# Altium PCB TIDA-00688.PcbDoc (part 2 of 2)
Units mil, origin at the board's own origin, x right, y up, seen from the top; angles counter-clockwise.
Board outline 1000 x 2450.32 mil, 4 copper layers (Top Layer, Signal Layer 1, Signal Layer 2, Bottom Layer), stack 61.6 mil thick; 78 components, 39 nets, 179 pads, 94 vias.
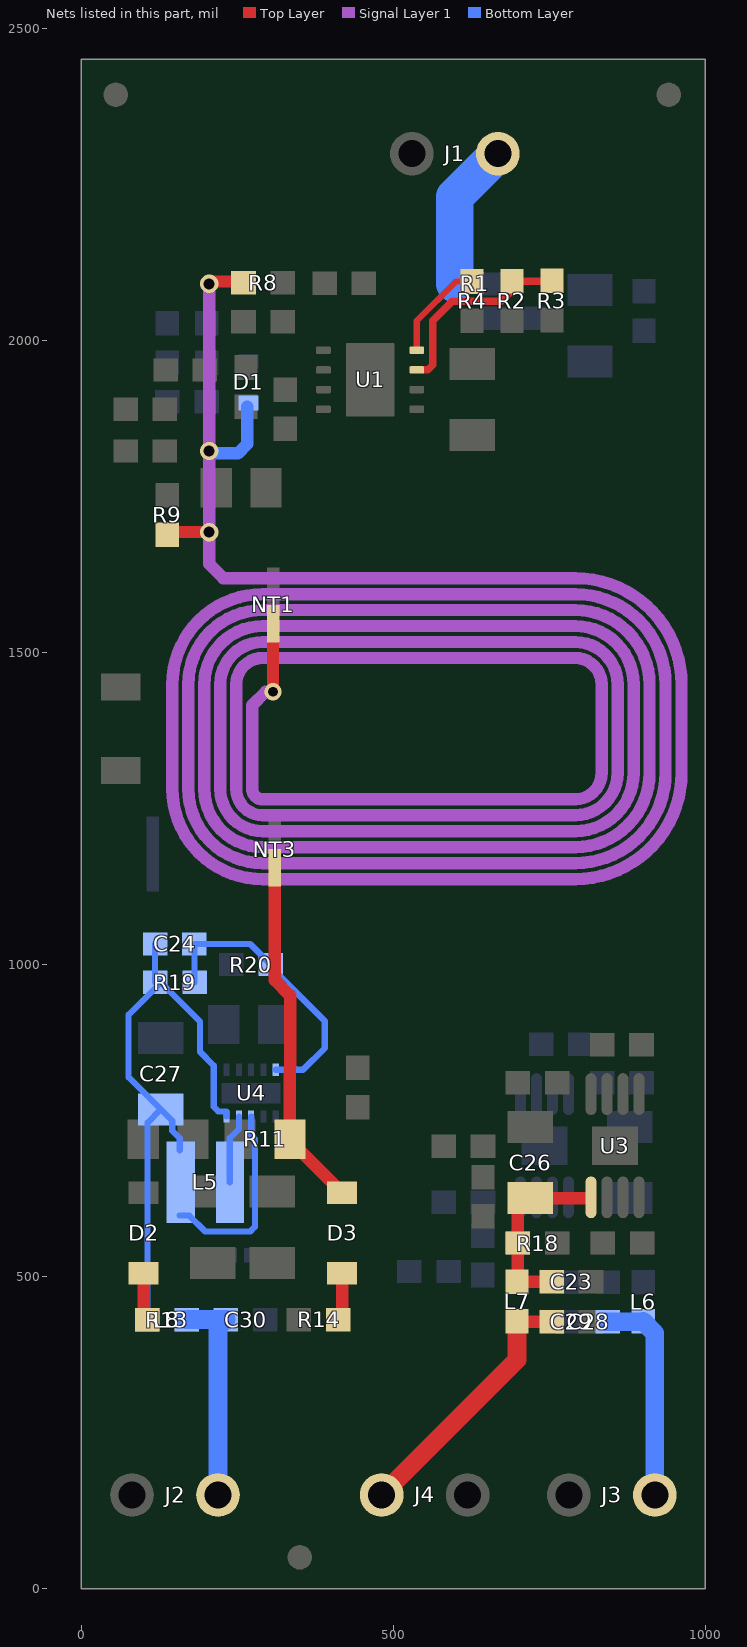
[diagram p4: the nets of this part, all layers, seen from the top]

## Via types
v1: diameter 26, hole 12, Top Layer to Bottom Layer, tented both sides, 55 vias
v2: diameter 20, hole 7.87, Top Layer to Bottom Layer, 10 vias
v3: diameter 29.53, hole 17.72, Top Layer to Bottom Layer, 8 vias
v4: diameter 20, hole 8, Top Layer to Bottom Layer, tented both sides, 7 vias
v5: diameter 19.68, hole 7.87, Top Layer to Bottom Layer, 6 vias
v6: diameter 23.62, hole 11.81, Top Layer to Bottom Layer, 3 vias
v7: diameter 26, hole 8, Top Layer to Bottom Layer, tented both sides, 2 vias
v8: diameter 24, hole 10, Top Layer to Bottom Layer, 1 vias
v9: diameter 20, hole 8, Top Layer to Bottom Layer, 1 vias
v10: diameter 27.56, hole 15.75, Top Layer to Bottom Layer, 1 vias

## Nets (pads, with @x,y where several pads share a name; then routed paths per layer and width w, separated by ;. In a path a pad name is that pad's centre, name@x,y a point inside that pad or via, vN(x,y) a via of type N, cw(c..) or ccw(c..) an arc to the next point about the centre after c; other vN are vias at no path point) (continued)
NetC23_2: C23.2 C26.1 L7.1 R18.2 U3.1 | length 296.5
  Top Layer w20: C23.2@753.5,491.7 700.5,491.7 699.5,492.7 R18.2@699.5,553.7 699.5,614.5 710.61,625.61 C26.1@719,625.61 U3.1@815.21,625.61
NetC24_1: C24.1 C27.1 L5.2 L8.1 R19.2 U4.8 U4.10 | length 1321.1
  Bottom Layer w10: L8.1@104.88,431 106,432.12 106,746.79 C27.1@127.13,767.91 ; C24.1@118.11,1032.89 118.11,971.67 R19.2@118.32,971.46 R19.2@127.59,971.46 ; L5.2@157.61,597.64 173.13,597.64 198.6,572.17 270.42,572.17 277.96,579.71 277.96,720.04 272,726 U4.8@272,756.6 ; L5.2@157.61,702.36 157.61,721.54 145.38,733.76 145.38,749.66 C27.1@127.13,767.91 ; U4.10@232.63,756.6 232.63,764.59 219.42,764.59 211.88,772.13 211.88,838.03 190.13,859.79 190.13,908.3 127.59,970.84 R19.2@127.59,971.46 ; C27.1@127.13,767.91 75.5,819.54 75.5,919.37 R19.2@127.59,971.46
NetC24_2: C24.2 R19.1 R20.2 U4.5 | length 459.7
  Bottom Layer w10: R19.1@181.32,971.46 181.31,1032.68 C24.2@181.1,1032.89 270.26,1032.89 R20.2@303.15,1000 303.15,996.06 389.76,909.45 389.76,866.14 355.02,831.4 U4.5@311.37,831.4
NetC28_1: C28.1 J3.2 L6.2 | length 398.7
  Bottom Layer w20: C28.1@843.5,427.7 L6.2@899.5,427.7
  Bottom Layer w30: C28.1@843.5,427.7 899.5,427.7 L6.2@900,428.2 918.9,409.31 J3.2@918.9,150
NetC29_1: C29.1 J4.1 L7.2 | length 423.1
  Top Layer w20: L7.2@698.7,427.7 C29.1@753.5,427.7
  Top Layer w30: J4.1@481.1,150 698,366.9 L7.2@698,428.5
NetC30_1: C30.1 J2.2 L8.2 | length 349.2
  Bottom Layer w30: L8.2@168.5,431 C30.1@231.5,431 218.9,418.39 J2.2@218.9,150
NetD1_2: D1.2 NT1.2 R8.2 R9.2 | length 12283.4
  Top Layer w19.68: R9.2@137.8,1688.98 141.73,1692.91 v3(204.72,1692.91) ; v3(204.72,2090.55) 208.68,2094.49 R8.2@259.84,2094.49 ; v10(307.09,1437.01) v10(307.09,1437.01) NT1.2@307.13,1546.33
  Signal Layer 1 w19.68: v3(204.72,2090.55) v3(204.72,1692.91) 204.72,1641.73 227.36,1619.09 791.34,1619.09 cw(c791.34,1448.82) 961.61,1448.82 961.61,1307.09 cw(c791.34,1307.09) 791.34,1136.81 290.35,1136.81 cw(c290.35,1281.5) 145.67,1281.5 145.67,1448.82 cw(c290.35,1448.82) 290.35,1593.5 791.34,1593.5 cw(c791.34,1448.82) 936.02,1448.82 936.02,1307.09 cw(c791.34,1307.09) 791.34,1162.4 290.35,1162.4 cw(c290.35,1281.5) 171.26,1281.5 171.26,1448.82 cw(c290.35,1448.82) 290.35,1567.91 791.56,1567.91 cw(c791.56,1449.04) 910.43,1449.04 910.43,1307.09 cw(c791.34,1307.09) 791.34,1187.99 290.35,1187.99 cw(c290.35,1281.5) 196.85,1281.5 196.85,1448.82 cw(c290.35,1448.82) 290.35,1542.32 791.34,1542.32 cw(c791.34,1448.82) 884.84,1448.82 884.84,1307.09 cw(c791.34,1307.09) 791.34,1213.58 290.35,1213.58 cw(c290.35,1281.5) 222.44,1281.5 222.44,1448.82 cw(c290.35,1448.82) 290.35,1516.73 791.34,1516.73 cw(c791.34,1448.82) 859.25,1448.82 859.25,1307.09 cw(c791.34,1307.09) 791.34,1239.17 290.35,1239.17 cw(c290.35,1281.5) 248.03,1281.5 248.03,1448.82 cw(c290.35,1448.82) 290.35,1491.14 791.34,1491.14 cw(c791.34,1448.82) 833.66,1448.82 833.66,1307.09 cw(c791.34,1307.09) 791.34,1264.76 290.25,1264.76 cw(c290.25,1281.5) 273.52,1281.5 273.52,1415.25 295.28,1437.01 v10(307.09,1437.01)
  Bottom Layer w19.68: v3(204.72,1822.83) 204.72,1818.9 204.92,1819.09 250.69,1819.09 265.75,1834.14 D1.2@265.75,1893.7
NetD2_1: D2.1 R13.2 | length 76.9
  Top Layer w20: D2.1@99.69,505.53 99.69,436.82 R13.2@105.5,431
NetD3_1: D3.1 NT3.2 R11.2 | length 563.3
  Top Layer w20: NT3.2@309.94,1155.04 309.94,974.97 334.49,950.42 R11.2@334,720 ; R11.2@334.11,717.96 D3.1@417.6,634.47
NetD3_2: D3.2 R14.2 | length 77.1
  Top Layer w20: R14.2@411.5,431 417.6,437.1 D3.2@417.6,505.53
NetJ1_1: J1.1 R1.2 | length 237.2
  Bottom Layer w60: R1.2@598.43,2090.55 598.43,2230.32 J1.1@667.32,2299.21
NetL5_1: L5.1 U4.9 | length 111.6
  Bottom Layer w10: L5.1@237.87,651 237.87,721.87 252.32,736.32 U4.9@252.31,756.6
NetR2_1: R2.1 R3.2 U1.3 | length 326.1
  Top Layer w11.81: U1.3@537.4,1952.75 555.11,1952.75 562.99,1960.63 562.99,2031.5 594.49,2062.99 673.23,2062.99 689.9,2079.67 R2.1@689.9,2094.85 753.31,2094.85 R3.2@753.94,2095.47
NetR4_2: R4.2 U1.4 | length 161.9
  Top Layer w10: U1.4@537.4,1984.25 537.4,2031.5 600.39,2094.49 R4.2@625.98,2094.49
pads on no net: FID1.1 FID2.1 FID3.1 U2.3 U2.7 U3.3 U3.7 U4.4

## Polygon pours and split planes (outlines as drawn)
GNDS on Bottom Layer "Top Layer-No Net 1" (solid, remove dead copper, shelved, pour order 17): 7.02,1075.61 7.02,1326.7 12.99,1332.67 93.19,1332.67 94.61,1331.24 94.61,1113.83 94.61,1112.4 82.85,1100.64 83.21,1100.28 83.21,1075.61
GND on Bottom Layer "Top Layer-No Net" (solid, remove dead copper, pour order 20): 15.26,1420.89 97.94,1420.89 101.88,1424.82 101.88,1538.22 220.48,1656.82 322.06,1656.82 326.28,1661.04 326.28,1767.34 381.4,1822.46 976,1822.46 987.7,1834.16 987.7,2111.99 973.67,2126.02 29.59,2126.02 11.32,2107.76 11.32,1432.7 23.14,1420.89
GNDS on Bottom Layer "Top Layer-No Net 3" (solid, remove dead copper, pour order 18): 0,1082.68 0,401.14 552,401.14 552,1082.68
GNDA on Bottom Layer "Top Layer-No Net 2" (solid, remove dead copper, pour order 14): 447,394.62 1000,394.62 1000,410 447,410
GNDA on Bottom Layer "Bottom Layer-No Net 1" (solid, remove dead copper, pour order 12): 1000,944.88 557,944.88 557,400 1000,400
GND on Top Layer "Top Layer-No Net" (solid, remove dead copper, pour order 19): 93.56,1420.94 102.36,1429.74 102.36,1539.37 220.06,1657.07 322.31,1657.07 326.28,1661.04 326.28,1767.47 381.65,1822.83 866.14,1822.83 976.38,1822.83 988.19,1834.65 988.19,2111.51 973.36,2126.33 29.9,2126.33 11.81,2108.24 11.81,1432.21 23.08,1420.94
GNDA on Top Layer "Top Layer-No Net 2" (solid, remove dead copper, pour order 13): 447,400 1000,400 1000,420 447,420
GNDA on Top Layer "Top Layer-GNDA" (solid, pour order 11): 1000,944.88 560,944.88 560,400 1000,400
GNDS on Top Layer "Top Layer-No Net 3" (solid, remove dead copper, pour order 15): 0,1082.68 0,400 552,400 552,1082.68
GNDS on Top Layer "Top Layer-No Net 1" (solid, remove dead copper, pour order 16): 7.02,1075.61 7.02,1326.7 12.99,1332.67 93.19,1332.67 94.61,1331.24 94.61,1113.83 94.61,1112.4 82.85,1100.64 83.21,1100.28 83.21,1075.61

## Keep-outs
Keep-Out Layer:
  lines w3.94: 0,0 1000,0 1000,2450.32 0,2450.32 0,0 ; 405.51,944.88 799.21,944.88 799.21,1102.36 405.51,1102.36 405.51,944.88 ; 405.51,1299.21 799.21,1299.21 799.21,1456.69 405.51,1456.69 405.51,1299.21 ; 405.51,1653.54 799.21,1653.54 799.21,1811.02 405.51,1811.02 405.51,1653.54
  lines w5: 359.7,3393.23 cw(c362.2,3393.23) 362.2,3395.73 ccw(c362.2,3393.23) 359.7,3393.23 ; 1000,2958.72 cw(c1000,2956.22) 1002.5,2956.22 ccw(c1000,2956.22) 1000,2958.72
  text ".Layer_Name" at 577,-858.49 h60

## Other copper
Top Layer:
  pour cut-out: 450,0 430,0 430,205.34 546,321.34 546,937.86 566.02,937.86 566.01,321.01 450,205 450,118
  pour cut-out: 409.45,944.88 362.2,944.88 326.77,980.32 326.77,1102.36 409.45,1102.36
  text ".CopyrightYear" at 133.86,2248.03 h60
  text "©" at 39.37,2244.09 h105
  text "TI" at 43.31,2157.48 h60
  text ".Layer_Name" at 577,-858.49 h60
Bottom Layer:
  pour cut-out: 450,0 430,0 430,205.34 546,321.34 546,937.86 566.02,937.86 566.01,321.01 450,205 450,118
  pour cut-out: 409.45,944.88 362.2,944.88 326.77,980.32 326.77,1102.36 409.45,1102.36
  text "GERMANY" at 22.44,2426.46 h60 r180
  text "MADE IN" at 22.44,2336.46 h60 r180
  text "UL94V-0" at 22.44,2246.46 h60 r180
  text ".Layer_Name" at 577,-858.49 h60

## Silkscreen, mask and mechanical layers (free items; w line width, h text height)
Top Overlay:
  circle w10: c181.1,1641.73 r5.57
  circle w10: c137.8,1133.86 r5.57
  circle w10: c263.78,1106.3 r5.57
  lines w7: 0,400 1000,400 1000,2125.98 0,2125.98 0,400
  text "GND" at 389.08,2421.24 h40 r270
  text "Vin" at 783.46,2420.43 h40 r270
  text ".PCB_Rev" at 831.7,1590.21 h60 r270
  text ".PRJ_Number" at 916.53,1590.49 h60 r270
  text "-15" at 465.98,391.51 h35 r270
  text "+15" at 848.26,390.77 h35 r270
  text "+5" at 169.06,375.92 h35 r270
  text "0" at 81.47,356.62 h35 r270
  text "0" at 575.1,331.38 h35 r90
  text "0" at 799.21,330.71 h35 r90
  text ".Layer_Name" at 577,-858.49 h60
Bottom Overlay:
  text ".Layer_Name" at 577,-858.49 h60
Top Paste:
  text ".Layer_Name" at 577,-858.49 h60
Bottom Paste:
  text ".Layer_Name" at 577,-858.49 h60
Top Solder:
  text ".Layer_Name" at 577,-858.49 h60
  text ".Layer_Name" at 577,-858.49 h60
Bottom Solder:
  text ".Layer_Name" at 577,-858.49 h60
Drill Guide:
  text ".Layer_Name" at 577,-858.49 h60
M1 Board Outline:
  lines w3.94: 405.51,944.88 799.21,944.88 ; 405.51,944.88 405.51,1102.36 ; 405.51,944.88 405.51,1102.36 ; 405.51,944.88 799.21,944.88 ; 405.51,1102.36 799.21,1102.36 ; 405.51,1102.36 799.21,1102.36 ; 405.51,1299.21 799.21,1299.21 ; 405.51,1299.21 405.51,1456.69 ; 405.51,1299.21 405.51,1456.69 ; 405.51,1299.21 799.21,1299.21 ; 405.51,1456.69 799.21,1456.69 ; 405.51,1456.69 799.21,1456.69 ; 405.51,1653.54 799.21,1653.54 ; 405.51,1653.54 405.51,1811.02 ; 405.51,1653.54 405.51,1811.02 ; 405.51,1653.54 799.21,1653.54 ; 405.51,1811.02 799.21,1811.02 ; 405.51,1811.02 799.21,1811.02 ; 799.21,944.88 799.21,1102.36 ; 799.21,944.88 799.21,1102.36 ; 799.21,1299.21 799.21,1456.69 ; 799.21,1299.21 799.21,1456.69 ; 799.21,1653.54 799.21,1811.02 ; 799.21,1653.54 799.21,1811.02 ; 0,0 0,2450.32 1000,2450.32 1000,0 0,0
  text ".Layer_Name" at 577,-858.49 h60
M2 Board Dimensions:
  rectangle: 0,-275 125,-150
  rectangle: 125,-400 500,-275
  lines w7: 0,-275 1000,-275 ; 125,-400 125,-150 ; 250,-400 250,-150 ; 500,-400 500,-150 ; 750,-400 750,-150 ; 0,-400 1000,-400 1000,-150 0,-150 0,-400
  text ".Layer_Name" at 577,-858.49 h60
M3 3D STEP Top:
  text ".Layer_Name" at 577,-858.49 h60
M4 3D STEP Bottom:
  text ".Layer_Name" at 577,-858.49 h60
M5 Assembly Top:
  lines w10: -292,-930.17 6308,-930.17 ; -292,-726.83 6310,-726.83 ; -292,-523.5 -292,-1133.5 3713,-1133.5 6310,-1133.5 6310,-523.5 -291.5,-523.5 -291.5,-1133.5 1284,-1133.5 ; 2173,-1133.5 2173,-523.5 ; 3440,-726.83 3440,-523.5 ; 4280,-726.83 4280,-523.5 ; 4902,-1140 4902,-937.17
  text "COMPONENTS MARKED 'DNP' SHOULD NOT BE POPULATED." at 1153.5,-318.5 h60
  text "ASSEMBLY VARIANT:" at 1153,-434 h60
  text ".VariantName" at 2189,-434 h60
  text "PCB VIEWED FROM TOP SIDE" at -228.5,-655.67 h60
  text "BOARD #:" at 2248,-655.67 h60
  text ".PRJ_Number" at 2793.5,-655.67 h60
  text "REV:" at 3638,-655.67 h60
  text ".PCB_Rev" at 3929.5,-655.67 h60
  text "SVN REV:" at 4476,-655.67 h60
  text ".VersionControl_RevNumber" at 4982,-655.67 h60
  text "PLOT NAME =" at -228.5,-1064.34 h60
  text ".plot_File_Name" at 577,-1064.34 h60
  text "GENERATED    :" at 2250,-1064.34 h60
  text ".Print_Date" at 3119.5,-1064.34 h60
  text ".Print_Time" at 3848.5,-1064.34 h60
  text "TEXAS INSTRUMENTS" at 5113,-1064.34 h60
M6 Assembly Bottom:
  lines w10: -292.5,-727.33 6309.5,-727.33 ; -290.5,-930.67 6309.5,-930.67 ; 1115.5,-1140.5 1115.5,-937.67 ; 1737.5,-727.33 1737.5,-524 ; 2577.5,-727.33 2577.5,-524 ; 3844.5,-1134 3844.5,-524 ; 4733.5,-1134 6309,-1134 6309,-524 -292.5,-524 -292.5,-1134 2304.5,-1134 6309.5,-1134 6309.5,-524
  text "COMPONENTS MARKED 'DNP' SHOULD NOT BE POPULATED." at 6102,-318 h60
  text ".VariantName" at 5058,-434 h60
  text "ASSEMBLY VARIANT:" at 6097,-434 h60
  text ".VersionControl_RevNumber" at 1035.5,-656.17 h60
  text "SVN REV:" at 1541.5,-656.17 h60
  text ".PCB_Rev" at 2088,-656.17 h60
  text "REV:" at 2379.5,-656.17 h60
  text ".PRJ_Number" at 3224,-656.17 h60
  text "BOARD #:" at 3769.5,-656.17 h60
  text "PCB VIEWED FROM BOTTOM SIDE" at 6246,-656.17 h60
  text "TEXAS INSTRUMENTS" at 904.5,-1064.84 h60
  text ".Print_Time" at 2169,-1064.84 h60
  text ".Print_Date" at 2898,-1064.84 h60
  text "GENERATED    :" at 3767.5,-1064.84 h60
  text ".plot_File_Name" at 5440.5,-1064.84 h60
  text "PLOT NAME =" at 6246,-1064.84 h60
M9 Title Sheet:
  drawing of 57 lines, arcs and shapes, not listed
  text "1" at 739.84,8036.5 h70
  text "2" at 3235.5,8036.5 h70
  text "3" at 5724.84,8036.5 h70
  text "4" at 8231.51,8036.5 h70
  text "5" at 10730.5,8036.5 h70
  text "6" at 13235.5,8036.5 h70
  text "A" at -416.5,6893.5 h70
  text "A" at 14383.5,6893.5 h70
  text "B" at -416.5,4513.5 h70
  text "B" at 14383.5,4513.5 h70
  text "C" at -416.5,2138.5 h70
  text "C" at 14383.5,2138.5 h70
  text "PROJECT TITLE:" at 11343.5,277.5 h45
  text ".PRJ_Title" at 11393.5,144.17 h70
  text "DESIGNED FOR:" at 11343.5,-23.5 h45
  text ".PRJ_Customer" at 11393.5,-163.5 h70
  text "D" at -416.5,-231.5 h70
  text "D" at 14383.5,-231.5 h70
  text "FILE NAME:" at 11343.5,-323.5 h45
  text ".PCB_File_Name_No_Path" at 11393.5,-443.5 h70
  text "Texas Instruments (TI) and/or its licensors do not warrant the accuracy or completeness of this specification" at 6374,-605.34 h45
  text "ENGINEER:" at 11343.5,-613.5 h45
  text "LAYOUT BY:" at 12848.5,-613.5 h45
  text "or any information contained therein. TI and/or its licensors do not warrant that this design will meet" at 6329.01,-718 h45
  text ".PRJ_Engineer" at 11393.5,-768.49 h70
  text ".PCB_Layout" at 12899,-768.49 h70
  text "the specifications, will be suitable for your application or fit for any particular purpose, or will operate in" at 6329.01,-830.67 h45
  text ".Layer_Name" at 577,-858.49 h60
  text "ALTIUM DESIGNER VERSION:" at 12848.5,-923.5 h45
  text "an implementation. TI and/or its licensors do not warrant that the design is production worthy. You should" at 6329.01,-943.34 h45
  text "completely validate and test your design implementation to confirm the system functionality for your application." at 6374,-1056 h45
  text ".print_Scale" at 11393.5,-1056.83 h70
  text ".Application_BuildNumber" at 12899,-1056.83 h70
  text "1" at 739.84,-1263.5 h70
  text "2" at 3235.5,-1263.5 h70
  text "3" at 5724.84,-1263.5 h70
  text "4" at 8231.51,-1263.5 h70
  text "5" at 10730.5,-1263.5 h70
  text "6" at 13235.5,-1263.5 h70
M10 Fab Notes:
  drawing of 185 lines, arcs and shapes, not listed
  text "DESIGN INFORMATION" at 12381.02,5910 h60
  text "MIN. TRACK WIDTH:" at 11736.46,5730 h60
  text "8" at 12832.7,5730 h60
  text "MIL" at 12987.46,5730 h60
  text "MIN. CLEARANCE:" at 11736.46,5598 h60
  text "0.2" at 12772.7,5598 h60
  text "mm" at 12987.46,5598 h60
  text "MIN. VIA PAD SIZE:" at 11736.46,5466 h60
  text "24" at 12802.71,5466 h60
  text "MIL" at 12987.46,5466 h60
  text "0.05mm (2MIL)" at 12431.46,5324.29 h60
  text "MINIMUM ANNULAR RING" at 11407.23,5320 h60
  text "EXTERNAL" at 13139.46,5320 h60
  text "PER" at 11607.23,5202 h60
  text "IPC-D-275 CLASS 2 LEVEL C" at 11827.23,5202 h60
  text "MIL, HOLES" at 13315.46,5089.71 h60
  text "+/-" at 12923,5089 h60
  text "+/-" at 13777,5089 h60
  text "REGISTRATION TOLERANCES:" at 11407.23,5084 h60
  text "METAL" at 12607,5084 h60
  text "5" at 13183.2,5084 h60
  text "3" at 14016.2,5084 h60
  text "MIL" at 14132.46,5084 h60
  text "MATERIAL:" at 11332.46,4874.54 h60
  text "FR-4 High Tg" at 12318.9,4734.21 h60
  text "FR-408" at 11753.46,4725.64 h60
  text "X" at 12165.46,4725.64 h60
  text "OTHER" at 13241.46,4725.64 h60
  text "62 MIL (1.6mm) +/-10%" at 12073.56,4562.92 h60
  text "THICKNESS:" at 11407.23,4558.64 h60
  text "X" at 11945.4,4558.64 h60
  text "OTHER" at 13358.46,4558.64 h60
  text "TOLERANCE:" at 11407.23,4400.64 h60
  text "X" at 12246.53,4400.64 h60
  text "ANSI IPC-6012 TYPE 3 CLASS 2" at 12433.48,4400.64 h60
  text "OTHER +/-" at 12433.46,4244.64 h60
  text "BOW & TWIST:" at 11407.23,4087.64 h60
  text "X" at 12246.53,4087.64 h60
  text "ANSI IPC-6012 TYPE 3 CLASS 2" at 12433.48,4087.64 h60
  text "OTHER +/-" at 12433.46,3929.13 h60
  text "DRILLING:" at 11332.46,3790.64 h60
  text "REFERENCE:" at 11407.23,3673.64 h60
  text "X" at 12055.46,3673.64 h60
  text "AS SHOWN" at 12242.46,3673.64 h60
  text "X" at 12956.46,3673.64 h60
  text "NC_DRILL FILES" at 13093.46,3673.64 h60
  text "PTH MIN COPPER THICKNESS:" at 11407.23,3515.64 h60
  text "X" at 12757.46,3515.64 h60
  text "1MIL" at 12894.46,3515.64 h60
  text "OTHER" at 13391.46,3515.64 h60
  text "BOARD FINISH:" at 11332.46,3356.64 h60
  text "SILKSCREEN:" at 11487.68,3238.64 h60
  text "X" at 12436.46,3238.64 h60
  text "TOP" at 12562.46,3238.64 h60
  text "X" at 12946.46,3238.64 h60
  text "BOTTOM" at 13073.46,3238.64 h60
  text "SILKSCREEN COLOR:" at 11487.68,3071.64 h60
  text "X" at 12435.42,3071.64 h60
  text "WHITE" at 12562.46,3071.64 h60
  text "OTHER" at 13073.46,3071.64 h60
  text "SOLDER RESIST COLOR:" at 11487.68,2901.64 h60
  text "X" at 12055.42,2742.44 h60
  text "GREEN" at 12182.46,2742.44 h60
  text "BLUE" at 12773.46,2742.44 h60
  text "OTHER" at 13311.46,2742.44 h60
  text "IMMERSION GOLD (ENIG)" at 12393.46,2553.92 h60
  text "ENEPIG" at 13731,2550.64 h60
  text "SURFACE FINISH:" at 11332.46,2549.64 h60
  text "X" at 12206.51,2549.64 h60
  text "IMM. TIN/SILVER OR EQUIV" at 11662,2392.64 h60
  text "OTHER" at 13093.46,2392.64 h60
  text "ARRAY/PANEL:" at 11332.46,2213.64 h60
  text "CUT AND TRIM PER MECH LAYER 1" at 12393.46,2209.35 h60
  text "N.C. ROUTE" at 12393.46,2057.64 h60
  text "X" at 13072.46,2057.64 h60
  text "V. SCORE" at 13259.46,2057.64 h60
  text "CERTIFICATION:" at 11332.46,1920.64 h60
  text "MATERIALS AND WORKMANSHIP FOR ALL PCBS" at 12057.46,1920.64 h60
  text "TO MEET OR EXCEED THE REQUIREMENTS OF:" at 12057.46,1822.64 h60
  text "X" at 11683.96,1686.13 h60
  text "ANSI IPC-A-600F CLASS ->" at 11822.96,1686.13 h60
  text "X" at 13462.02,1686.13 h60
  text "2" at 13580.96,1686.13 h60
  text "1" at 13265.96,1684.64 h60
  text "3" at 13934.96,1684.64 h60
  text "X" at 11686.02,1526.64 h60
  text "UL 94V-0" at 11822.96,1526.64 h60
  text "X" at 12498.02,1526.64 h60
  text "RoHS" at 12634.96,1526.64 h60
  text "OTHER" at 13279.36,1526.64 h60
  text "PER ORDER" at 13676.42,1526.64 h60
  text "ADDITIONAL REQUIREMENTS:" at 11332.46,1385.64 h60
  text "MICROSECTION:" at 11407.23,1270.64 h60
  text "YES" at 12312.96,1270.64 h60
  text "REQUIRED" at 13174.46,1114.49 h60
  text "BARE BOARD ELEC. TEST:" at 11407.23,1111.64 h60
  text "NONE" at 12712.96,1111.64 h60
  text "X" at 13047.46,1111.64 h60
  text "PER ORDER" at 13766.46,1111.64 h60
  text "MANUFACTURER'S UL:" at 11407.23,954.64 h60
  text "RAIL" at 12572.96,950.35 h60
  text "METAL" at 13064.77,950.35 h60
  text "X" at 13440,950 h60
  text "SILK" at 13576.46,950.35 h60
  text ".Layer_Name" at 577,-858.49 h60
M11 Gerber Information:
  lines w10: -292,-930.17 6308,-930.17 ; -292,-726.83 6310,-726.83 ; -292,-523.5 -292,-1133.5 3713,-1133.5 6310,-1133.5 6310,-523.5 -291.5,-523.5 -291.5,-1133.5 1284,-1133.5 ; 2173,-1133.5 2173,-523.5 ; 3440,-726.83 3440,-523.5 ; 4280,-726.83 4280,-523.5 ; 4902,-1140 4902,-937.17
  text "ALL ARTWORK VIEWED FROM TOP SIDE" at -228.5,-655.67 h60
  text "BOARD #:" at 2248,-655.67 h60
  text ".PRJ_Number" at 2793.5,-655.67 h60
  text "REV:" at 3638,-655.67 h60
  text ".PCB_Rev" at 3929.5,-655.67 h60
  text "SVN REV:" at 4476,-655.67 h60
  text ".VersionControl_RevNumber" at 4982,-655.67 h60
  text "LAYER NAME =" at -228.5,-858.49 h60
  text "PLOT NAME =" at -228.5,-1064.34 h60
  text ".plot_File_Name" at 577,-1064.34 h60
  text "GENERATED    :" at 2250,-1064.34 h60
  text ".Print_Date" at 3119.5,-1064.34 h60
  text ".Print_Time" at 3848.5,-1064.34 h60
  text "TEXAS INSTRUMENTS" at 5113,-1064.34 h60
M12 Stackup:
  drawing of 191 lines, arcs and shapes, not listed
  text "Layer" at 9790.58,7830 h60
  text "Name" at 10200.49,7830 h60
  text "Material" at 11130.23,7830 h60
  text "Thickness" at 11990,7830 h60
  text "Constant" at 12639.83,7830 h60
  text "Board Layer Stack" at 13209.7,7830 h60
  text "1" at 9790.58,7710 h60
  text "Top Overlay" at 10200.49,7710 h60
  text "2" at 9790.58,7590 h60
  text "Top Solder" at 10200.49,7590 h60
  text "Solder Resist" at 11130.23,7590 h60
  text "0.40mil" at 11990,7590 h60
  text "3.5" at 12639.83,7590 h60
  text "3" at 9790.58,7470 h60
  text "Top Layer" at 10200.49,7470 h60
  text "Copper" at 11130.23,7470 h60
  text "1.40mil" at 11990,7470 h60
  text "4" at 9790.58,7350 h60
  text "Dielectric1" at 10200.49,7350 h60
  text "FR-4" at 11130.23,7350 h60
  text "59.20mil" at 11990,7350 h60
  text "4.8" at 12639.83,7350 h60
  text "5" at 9790.58,7230 h60
  text "Bottom Layer" at 10200.49,7230 h60
  text "Copper" at 11130.23,7230 h60
  text "1.40mil" at 11990,7230 h60
  text "6" at 9790.58,7110 h60
  text "Bottom Solder" at 10200.49,7110 h60
  text "Solder Resist" at 11130.23,7110 h60
  text "0.40mil" at 11990,7110 h60
  text "3.5" at 12639.83,7110 h60
  text "7" at 9790.58,6990 h60
  text "Bottom Overlay" at 10200.49,6990 h60
  text ".Layer_Name" at 577,-858.49 h60
M13 Component Bodies Top:
  text ".Layer_Name" at 577,-858.49 h60
M14 Component Bodies Bottom:
  text ".Layer_Name" at 577,-858.49 h60
M15 Courtyards Top:
  text ".Layer_Name" at 577,-858.49 h60
M16 Courtyards Bottom:
  text ".Layer_Name" at 577,-858.49 h60
Drill Drawing:
  circle w1: c5572.72,3221.04 r24.89
  lines w1: 5547.83,2163.36 5560.27,2163.36 5572.72,2150.92 5585.16,2163.36 5597.6,2163.36 5585.16,2175.8 5597.6,2188.25 5585.16,2188.25 5572.72,2200.69 5560.27,2188.25 5547.83,2188.25 5560.27,2175.8 5547.83,2163.36 ; 5547.83,2325.12 5572.72,2300.24 5597.6,2325.12 5572.72,2350.01 5547.83,2325.12 ; 5547.83,2462 5560.27,2462 5560.27,2449.56 5585.16,2449.56 5585.16,2462 5597.6,2462 5597.6,2486.89 5585.16,2486.89 5585.16,2499.33 5560.27,2499.33 5560.27,2486.89 5547.83,2486.89 5547.83,2462 ; 5547.83,2648.65 5597.6,2648.65 5572.72,2598.88 5547.83,2648.65 ; 5547.83,2748.2 5572.72,2760.64 5597.6,2748.2 5585.16,2773.08 5597.6,2797.97 5572.72,2785.53 5547.83,2797.97 5560.27,2773.08 5547.83,2748.2 ; 5547.83,2897.52 5597.6,2897.52 5597.6,2947.29 5547.83,2947.29 5547.83,2897.52 ; 5547.83,3046.84 5597.6,3046.84 5597.6,3096.61 5547.83,3096.61 5547.83,3046.84 ; 5557.78,2907.47 5587.65,2907.47 5587.65,2937.33 5557.78,2937.33 5557.78,2907.47
  lines w12: 5480,2106.12 7598.02,2106.12 ; 5480,3300.68 7598.02,3300.68 ; 5850.36,1956.8 5850.36,3450 ; 6207.36,1956.8 6207.36,3450 ; 6868.93,1956.8 6868.93,3450 ; 7153.07,1956.8 7153.07,3450 ; 5480,1956.8 7598.02,1956.8 7598.02,3450 5480,3450 5480,1956.8
  text "Symbol" at 5569.59,3345.48 h72
  text "Quantity" at 5895.16,3345.48 h72
  text "Finished Hole Size" at 6252.16,3345.48 h72
  text "Plated" at 6913.72,3345.48 h72
  text "Hole Type" at 7197.86,3345.48 h72
  text "16" at 5895.16,3196.16 h60
  text "7,87mil (0,200mm)" at 6252.16,3196.16 h60
  text "PTH" at 6913.72,3196.16 h60
  text "Round" at 7197.86,3196.16 h60
  text "10" at 5895.16,3046.84 h60
  text "8,00mil (0,203mm)" at 6252.16,3046.84 h60
  text "PTH" at 6913.72,3046.84 h60
  text "Round" at 7197.86,3046.84 h60
  text "1" at 5895.16,2897.52 h60
  text "10,00mil (0,254mm)" at 6252.16,2897.52 h60
  text "PTH" at 6913.72,2897.52 h60
  text "Round" at 7197.86,2897.52 h60
  text "3" at 5895.16,2748.2 h60
  text "11,81mil (0,300mm)" at 6252.16,2748.2 h60
  text "PTH" at 6913.72,2748.2 h60
  text "Round" at 7197.86,2748.2 h60
  text "55" at 5895.16,2598.88 h60
  text "12,00mil (0,305mm)" at 6252.16,2598.88 h60
  text "PTH" at 6913.72,2598.88 h60
  text "Round" at 7197.86,2598.88 h60
  text "1" at 5895.16,2449.56 h60
  text "15,75mil (0,400mm)" at 6252.16,2449.56 h60
  text "PTH" at 6913.72,2449.56 h60
  text "Round" at 7197.86,2449.56 h60
  text "8" at 5895.16,2300.24 h60
  text "17,72mil (0,450mm)" at 6252.16,2300.24 h60
  text "PTH" at 6913.72,2300.24 h60
  text "Round" at 7197.86,2300.24 h60
  text "8" at 5895.16,2150.92 h60
  text "43,31mil (1,100mm)" at 6252.16,2150.92 h60
  text "PTH" at 6913.72,2150.92 h60
  text "Round" at 7197.86,2150.92 h60
  text "102 Total" at 5895.16,2001.6 h60
  text ".Layer_Name" at 577,-858.49 h60

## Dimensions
0,-400 to 1000,-400 on M2 Board Dimensions
7.5,0.31 to 0,2450.32 on M2 Board Dimensions
0,0 to 1000,0 on M2 Board Dimensions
